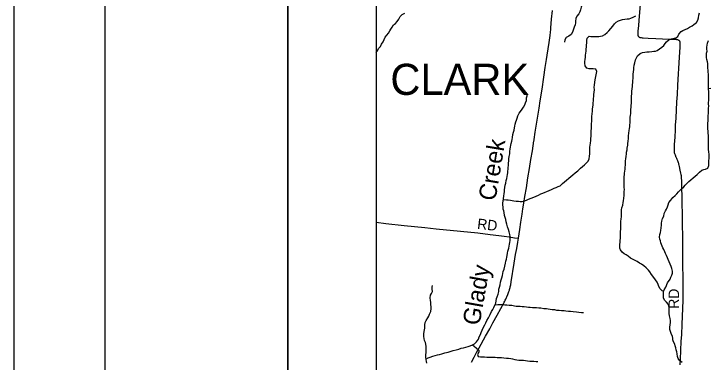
# Model space of a CAD drawing. Extents: x 0 to 1052, y -194 to 246.
# Drawn here: x 0 to 3.805, y 17.846 to 19.749 of the extents above; entities that cross this region are included whole.
import ezdxf

# ---------------------------------------------------------------- set-up
doc = ezdxf.new("R2010")
doc.units = 0
for name, color, linetype in [('GM_X_Corporation', 7, 'Continuous'), ('GM_X_County_Road', 7, 'Continuous'), ('GM_X_County_Road_Text', 7, 'Continuous'), ('GM_X_Minor_River', 7, 'Continuous'), ('GM_X_Minor_River_Text', 7, 'Continuous'), ('GM_X_Township_Road', 7, 'Continuous'), ('GM_X_Township_Road_Text', 7, 'Continuous'), ('GM_X_Township_Text', 7, 'Continuous'), ('SH_Border', 7, 'Continuous'), ('SH_Cut_Line', 7, 'Continuous')]:
    doc.layers.add(name, color=color, linetype=linetype)

msp = doc.modelspace()

# ---------------------------------------------------------------- linework, layer by layer
at = {"layer": 'GM_X_Corporation'}
for points in [[(5.1788, 17.6981), (5.491, 17.9457), (6.1888, 18.4644), (6.5994, 18.7694), (6.8785, 18.9763), (8.1871, 19.9814), (8.6571, 20.341), (8.7822, 20.435), (8.7822, 21.0055), (1.9822, 21.0055), (1.9822, 14.2055)], [(5.1788, 17.6981), (5.491, 17.9457), (6.1888, 18.4644), (6.152, 18.6129), (5.992, 19.3448), (5.9283, 19.6076), (5.6935, 20.5776), (5.5898, 21.0055), (1.9822, 21.0055), (1.9822, 14.2055)]]:
    msp.add_lwpolyline(points, dxfattribs=at)
at = {"layer": 'GM_X_County_Road'}
for points in [[(3.6466, 17.8318), (3.6482, 17.8609), (3.6507, 17.9105), (3.653, 17.9577), (3.6552, 17.9974), (3.6578, 18.0507), (3.6604, 18.0979), (3.6618, 18.1389), (3.6628, 18.1849), (3.6633, 18.2296), (3.6634, 18.2607), (3.6626, 18.3346), (3.6623, 18.3483), (3.6622, 18.3526), (3.6623, 18.3675), (3.662, 18.4222), (3.6617, 18.4899), (3.6611, 18.5303), (3.6599, 18.5999), (3.6591, 18.6558), (3.6579, 18.7117), (3.657, 18.7621), (3.6564, 18.7851), (3.6552, 18.841), (3.6548, 18.8498), (3.6546, 18.8534), (3.6542, 18.8582), (3.6538, 18.8621), (3.6533, 18.8656), (3.6529, 18.8683), (3.6524, 18.8708), (3.651, 18.8781), (3.6474, 18.8945), (3.6426, 18.9157), (3.6411, 18.9224), (3.6401, 18.9265), (3.639, 18.9309), (3.6375, 18.936), (3.636, 18.9411), (3.6344, 18.9454), (3.6328, 18.9499), (3.6309, 18.9542), (3.629, 18.9584), (3.6274, 18.9617), (3.6257, 18.9651), (3.6205, 18.9764), (3.6189, 18.9807), (3.6177, 18.9847), (3.6166, 18.9893), (3.6159, 18.9929), (3.6155, 18.9971), (3.6152, 19.0005), (3.615, 19.0039), (3.6151, 19.0092), (3.6152, 19.0132), (3.6156, 19.0206), (3.6164, 19.0349), (3.6187, 19.0764), (3.6207, 19.1149), (3.622, 19.141), (3.6241, 19.1788), (3.629, 19.2688), (3.6314, 19.3091), (3.6341, 19.36), (3.6429, 19.5125), (3.646, 19.5684), (3.647, 19.5815), (3.6471, 19.5865), (3.6472, 19.5903), (3.647, 19.5936), (3.6465, 19.5963), (3.6457, 19.5986), (3.6446, 19.6004), (3.6431, 19.6021), (3.6416, 19.6033), (3.6398, 19.6047), (3.6376, 19.6059), (3.6345, 19.6071), (3.6315, 19.6079), (3.6292, 19.6083), (3.6264, 19.6086), (3.5934, 19.6098), (3.5499, 19.6121), (3.5133, 19.6137), (3.4724, 19.6157), (3.4444, 19.6173), (3.4407, 19.6175), (3.4352, 19.6181), (3.4316, 19.6186), (3.4287, 19.6193), (3.4262, 19.6202), (3.4243, 19.6213), (3.4224, 19.6225), (3.4207, 19.6242), (3.419, 19.6264), (3.418, 19.6283), (3.4173, 19.6302), (3.4167, 19.6331), (3.4165, 19.635), (3.4163, 19.6373), (3.4164, 19.6404), (3.4164, 19.6428), (3.4169, 19.6484), (3.4176, 19.6552), (3.4202, 19.6855), (3.4225, 19.7127), (3.4324, 19.8272)], [(2.7611, 18.5232), (2.7689, 18.5716), (2.7753, 18.6114), (2.782, 18.6544), (2.7864, 18.6839), (2.7915, 18.7152), (2.797, 18.7508), (2.8049, 18.7992), (2.8138, 18.8538), (2.8223, 18.9047), (2.8298, 18.9526), (2.8378, 19.001), (2.8463, 19.056), (2.8469, 19.0593), (2.8475, 19.063), (2.8539, 19.1029), (2.8594, 19.1353), (2.8694, 19.2004), (2.8743, 19.2336), (2.8806, 19.2748), (2.8906, 19.3386), (2.9007, 19.4043), (2.9085, 19.456), (2.912, 19.4787), (2.9152, 19.5002), (2.919, 19.5247), (2.9295, 19.5935), (2.9346, 19.6311), (2.9368, 19.6488), (2.9374, 19.6539), (2.9381, 19.6604), (2.9393, 19.673), (2.9433, 19.7201), (2.948, 19.7683)], [(2.5041, 17.8459), (2.5187, 17.8727), (2.5324, 17.8977), (2.5464, 17.9234), (2.5817, 17.9869), (2.6044, 18.0283), (2.6218, 18.0599), (2.6455, 18.1022), (2.6653, 18.1388), (2.6816, 18.1688), (2.6842, 18.1739), (2.687, 18.1794), (2.6895, 18.1843), (2.6921, 18.1897), (2.6964, 18.1988), (2.6984, 18.2034), (2.7034, 18.2147), (2.7077, 18.2257), (2.7098, 18.2316), (2.711, 18.235), (2.7124, 18.2396), (2.7135, 18.2433), (2.7147, 18.2479), (2.716, 18.2529), (2.7171, 18.258), (2.718, 18.2626), (2.7191, 18.2686), (2.7202, 18.2749), (2.7209, 18.2791), (2.7219, 18.2853), (2.7383, 18.3864), (2.746, 18.4337), (2.752, 18.4673), (2.7578, 18.5022), (2.7611, 18.5232)]]:
    msp.add_lwpolyline(points, dxfattribs=at)
at = {"layer": 'GM_X_Minor_River'}
for points in [[(3.1551, 19.8769), (3.1466, 19.8642), (3.1365, 19.8514), (3.1295, 19.8386), (3.124, 19.825), (3.1151, 19.8122), (3.1089, 19.7993), (3.1049, 19.7865), (3.1005, 19.7717), (3.0977, 19.7611), (3.0923, 19.7502), (3.0815, 19.7374), (3.0763, 19.725), (3.0743, 19.7102), (3.073, 19.7003), (3.0717, 19.6905), (3.0666, 19.6761), (3.0611, 19.6614), (3.0567, 19.6497), (3.0501, 19.6369), (3.0371, 19.6275), (3.0233, 19.6205), (3.0163, 19.6073), (3.0139, 19.5952)], [(1.9822, 19.5386), (1.9877, 19.5466), (1.9966, 19.5613), (2.0062, 19.5714), (2.0124, 19.5831), (2.0214, 19.5959), (2.0265, 19.6091), (2.0327, 19.6227), (2.0416, 19.6332), (2.0505, 19.6445), (2.0579, 19.6562), (2.0637, 19.6667), (2.0703, 19.6776), (2.0781, 19.6901), (2.088, 19.6975), (2.0977, 19.7073), (2.1062, 19.7208), (2.1148, 19.7359), (2.1259, 19.7464), (2.1389, 19.7542)], [(3.3877, 19.3736), (3.3882, 19.3842), (3.3892, 19.3979), (3.3897, 19.4096), (3.3902, 19.4203), (3.3915, 19.432), (3.3925, 19.4453), (3.393, 19.4548), (3.3954, 19.4684), (3.3987, 19.4824), (3.4023, 19.4983), (3.4074, 19.51), (3.414, 19.5202), (3.4274, 19.5329), (3.4415, 19.5377), (3.4541, 19.5409), (3.4648, 19.5415), (3.4766, 19.5421), (3.4921, 19.5438), (3.502, 19.5448), (3.5115, 19.5462), (3.5215, 19.5491), (3.5345, 19.5577), (3.5464, 19.5667), (3.5572, 19.5772), (3.5645, 19.5869), (3.5715, 19.5975), (3.5861, 19.6098), (3.6002, 19.6138), (3.6139, 19.6159), (3.6234, 19.6188), (3.6338, 19.6263), (3.6389, 19.638), (3.6524, 19.6537), (3.6619, 19.6586), (3.6738, 19.6633), (3.6875, 19.6696), (3.6983, 19.6763), (3.7116, 19.6841), (3.7224, 19.6908), (3.7354, 19.7024), (3.7436, 19.7148), (3.7468, 19.7281), (3.7496, 19.7421), (3.7532, 19.7557)], [(3.1916, 19.6255), (3.2011, 19.6266), (3.211, 19.6283), (3.2213, 19.6297), (3.2343, 19.636), (3.2478, 19.6476), (3.2566, 19.6574), (3.267, 19.6694), (3.2779, 19.6825), (3.2871, 19.6957), (3.2971, 19.705), (3.3086, 19.7117), (3.3205, 19.7157), (3.3311, 19.7183), (3.3441, 19.72), (3.3562, 19.7217), (3.3673, 19.7231), (3.3776, 19.7264), (3.3902, 19.7315), (3.4039, 19.7382)], [(2.6791, 18.7342), (2.6958, 18.7334), (2.7061, 18.7325), (2.7178, 18.7305), (2.7277, 18.7292), (2.7372, 18.7275), (2.7493, 18.7266), (2.7611, 18.7257), (2.7717, 18.7241), (2.7812, 18.7232), (2.7945, 18.7268), (2.8052, 18.732), (2.8167, 18.736), (2.8319, 18.7426), (2.8453, 18.7482), (2.8579, 18.7529), (2.8705, 18.7581), (2.8847, 18.7655), (2.8942, 18.7692), (2.908, 18.7747), (2.9175, 18.7791), (2.9297, 18.7847), (2.9424, 18.7902), (2.9573, 18.7972), (2.968, 18.8012), (2.9798, 18.8056), (2.9901, 18.8101), (3.0024, 18.8217), (3.0128, 18.8314), (3.0239, 18.8396), (3.037, 18.852), (3.0485, 18.8602), (3.06, 18.8699), (3.0727, 18.88), (3.0861, 18.8912), (3.1015, 18.9062), (3.1115, 18.9152), (3.1223, 18.9249), (3.1327, 18.9327), (3.1431, 18.944), (3.1493, 18.9568), (3.1514, 18.9716), (3.1524, 18.9849), (3.1527, 19.008), (3.1532, 19.0205), (3.1545, 19.0315), (3.1554, 19.0422), (3.1571, 19.0577), (3.1584, 19.0683), (3.1593, 19.0808), (3.1605, 19.1104), (3.1614, 19.1226), (3.1616, 19.1381), (3.1621, 19.148), (3.1631, 19.1632), (3.1636, 19.1761), (3.1642, 19.1905), (3.1655, 19.2015), (3.1665, 19.2189), (3.1678, 19.2307), (3.169, 19.2401), (3.17, 19.2523), (3.1712, 19.2625), (3.1725, 19.275), (3.1731, 19.2868), (3.1744, 19.2978), (3.1749, 19.308), (3.1762, 19.3209), (3.1771, 19.3349), (3.1769, 19.3482), (3.1775, 19.3604), (3.18, 19.3759), (3.182, 19.3884), (3.1837, 19.3983), (3.1861, 19.4081), (3.1894, 19.4251), (3.1906, 19.4354), (3.1847, 19.4468), (3.1714, 19.4485), (3.1619, 19.4486), (3.149, 19.4496), (3.1362, 19.4535), (3.1261, 19.4647), (3.1248, 19.4799), (3.1256, 19.4894), (3.1273, 19.5), (3.1286, 19.5132), (3.1291, 19.5239), (3.1304, 19.5341), (3.1321, 19.5466), (3.133, 19.5568), (3.1335, 19.569), (3.1344, 19.5792), (3.1353, 19.591), (3.1367, 19.6046), (3.1383, 19.6167), (3.1484, 19.6272), (3.1578, 19.6267), (3.1715, 19.6262), (3.181, 19.6257), (3.1916, 19.6255)], [(3.5406, 18.5649), (3.5431, 18.5804), (3.5448, 18.5945), (3.5446, 18.6055), (3.5459, 18.6172), (3.5506, 18.6308), (3.5565, 18.644), (3.5601, 18.6588), (3.566, 18.672), (3.5718, 18.6826), (3.5766, 18.6954), (3.5813, 18.706), (3.5856, 18.7185), (3.5953, 18.7305), (3.6073, 18.7463), (3.6188, 18.756), (3.6284, 18.7661), (3.638, 18.7759), (3.6523, 18.792), (3.6661, 18.8032), (3.6739, 18.8134), (3.6843, 18.8242), (3.695, 18.834), (3.705, 18.8429), (3.7177, 18.8538), (3.7288, 18.8628), (3.7392, 18.8706), (3.7527, 18.8848), (3.7661, 18.8945), (3.7757, 18.899), (3.7852, 18.9004), (3.7982, 18.9059), (3.8029, 18.9199), (3.8039, 18.9358), (3.8044, 18.9487), (3.805, 18.9589), (3.8047, 18.9715), (3.8049, 18.9817), (3.8039, 18.9946), (3.8026, 19.0083), (3.8023, 19.0193), (3.8018, 19.0342), (3.8015, 19.0444), (3.8017, 19.0539), (3.8014, 19.0649), (3.8016, 19.0771), (3.801, 19.0866), (3.8007, 19.0964), (3.7997, 19.1075), (3.7991, 19.1204), (3.7981, 19.1306), (3.7979, 19.1413), (3.7984, 19.1538), (3.7997, 19.1633), (3.8002, 19.1731), (3.8, 19.1834), (3.8005, 19.1929), (3.8018, 19.2061), (3.802, 19.2213), (3.8025, 19.2316), (3.8031, 19.246), (3.8024, 19.2555), (3.8022, 19.2657), (3.8031, 19.2756), (3.804, 19.2858), (3.8042, 19.3048), (3.8036, 19.3147), (3.803, 19.3257), (3.8024, 19.3371), (3.8025, 19.347), (3.8023, 19.3565), (3.8017, 19.3694), (3.8026, 19.3807), (3.802, 19.3918), (3.8014, 19.4054), (3.8012, 19.4202), (3.8006, 19.4301), (3.8, 19.4427), (3.7986, 19.4522), (3.798, 19.4658), (3.7974, 19.478), (3.7964, 19.4883), (3.7932, 19.5008), (3.7918, 19.5103), (3.7904, 19.5248), (3.7917, 19.5343), (3.7941, 19.5464), (3.7935, 19.557), (3.7929, 19.5673), (3.7946, 19.5779), (3.7962, 19.5892), (3.8017, 19.6032)], [(3.5563, 18.233), (3.548, 18.2364), (3.5367, 18.2461), (3.5293, 18.2598), (3.5264, 18.2694), (3.5209, 18.282), (3.5123, 18.2961), (3.5026, 18.3092), (3.4903, 18.3241), (3.4806, 18.3387), (3.4728, 18.3486), (3.4616, 18.3621), (3.4484, 18.3729), (3.4352, 18.3818), (3.4243, 18.3876), (3.4115, 18.3954), (3.4006, 18.4016), (3.3889, 18.4074), (3.3753, 18.4148), (3.3629, 18.4256), (3.3512, 18.4326), (3.3407, 18.4384), (3.3286, 18.4477), (3.3201, 18.4596), (3.3171, 18.4691), (3.3169, 18.4786), (3.3174, 18.4904), (3.3183, 18.5002), (3.3192, 18.5116), (3.3197, 18.5215), (3.3199, 18.5359), (3.3194, 18.5496), (3.3203, 18.5609), (3.3212, 18.5715), (3.3213, 18.5826), (3.3219, 18.5943), (3.322, 18.6068), (3.3229, 18.6167), (3.3242, 18.6277), (3.3248, 18.6414), (3.3253, 18.6558), (3.3259, 18.6679), (3.3264, 18.6789), (3.3277, 18.6895), (3.3321, 18.7035), (3.3357, 18.7179), (3.3369, 18.7277), (3.3379, 18.7414), (3.3396, 18.7558), (3.3405, 18.766), (3.3407, 18.7793), (3.3412, 18.7896), (3.3406, 18.7998), (3.3403, 18.8116), (3.3397, 18.8241), (3.3407, 18.8359), (3.3404, 18.848), (3.3402, 18.8598), (3.3419, 18.8697), (3.3428, 18.8795), (3.3437, 18.8905), (3.3453, 18.9004), (3.3466, 18.9114), (3.3471, 18.9216), (3.3477, 18.9337), (3.3482, 18.9463), (3.3495, 18.9576), (3.3508, 18.9705), (3.3529, 18.9838), (3.3538, 18.9933), (3.3562, 19.0061), (3.3571, 19.0156), (3.3596, 19.0315), (3.3609, 19.0418), (3.3622, 19.0531), (3.3631, 19.0683), (3.3645, 19.0827), (3.3666, 19.0967), (3.3675, 19.1115), (3.3699, 19.1225), (3.3708, 19.1328), (3.3713, 19.1426), (3.3726, 19.154), (3.3735, 19.1638), (3.3738, 19.184), (3.3747, 19.1934), (3.376, 19.2044), (3.3765, 19.2147), (3.3774, 19.228), (3.3783, 19.2374), (3.3788, 19.2484), (3.3801, 19.2606), (3.38, 19.2761), (3.3805, 19.2868), (3.3806, 19.2989), (3.3823, 19.3122), (3.3829, 19.327), (3.3835, 19.3391), (3.3851, 19.352), (3.386, 19.3618), (3.3877, 19.3736)], [(3.8025, 19.3424), (3.8154, 19.3426)], [(2.7082, 18.9451), (2.7095, 18.9564), (2.7115, 18.9705), (2.714, 18.9837), (2.7149, 18.997), (2.7166, 19.011), (2.7179, 19.0216), (2.72, 19.0315), (2.7224, 19.0413), (2.7248, 19.053), (2.7268, 19.0636), (2.7285, 19.0743), (2.7317, 19.0902), (2.735, 19.103), (2.7374, 19.1136), (2.7398, 19.1257), (2.7422, 19.1363), (2.7443, 19.1466), (2.7475, 19.1587), (2.7506, 19.1685), (2.7538, 19.1795), (2.7582, 19.1931), (2.7648, 19.2063), (2.7729, 19.2164), (2.7815, 19.2285), (2.7892, 19.2401), (2.7966, 19.2526), (2.8009, 19.2635), (2.8049, 19.2767), (2.8066, 19.29), (2.8094, 19.3017), (2.8107, 19.3116)], [(2.2555, 17.8624), (2.2679, 17.8696), (2.2786, 17.8725), (2.2927, 17.8776), (2.3053, 17.8816), (2.3179, 17.8853), (2.3286, 17.8878), (2.3419, 17.8914), (2.3587, 17.8957), (2.3762, 17.9008), (2.3877, 17.9033), (2.4052, 17.9088), (2.4212, 17.9135), (2.4361, 17.9175), (2.4479, 17.9212), (2.4601, 17.9248), (2.4731, 17.9284), (2.486, 17.9313), (2.4979, 17.9353), (2.5109, 17.9405), (2.5219, 17.946), (2.5327, 17.9573), (2.5428, 17.9716), (2.5468, 17.984), (2.5538, 17.9965), (2.5577, 18.0082), (2.5628, 18.0207), (2.5703, 18.0361), (2.5773, 18.0501), (2.5827, 18.0603), (2.5886, 18.0739), (2.5975, 18.0882), (2.6065, 18.107), (2.6147, 18.1217), (2.621, 18.1342), (2.6272, 18.1451), (2.6327, 18.1579), (2.637, 18.1681), (2.6415, 18.1931), (2.6454, 18.203), (2.6509, 18.2177), (2.6534, 18.2313), (2.6551, 18.2438), (2.6579, 18.2548), (2.6611, 18.2692), (2.664, 18.2828), (2.6672, 18.2957), (2.6704, 18.3063), (2.6743, 18.3191), (2.6768, 18.3297), (2.6781, 18.3411), (2.6832, 18.3543), (2.6872, 18.3698), (2.6912, 18.3861), (2.6932, 18.3982), (2.6957, 18.4084), (2.6985, 18.4194), (2.6997, 18.4289), (2.7018, 18.4406), (2.7039, 18.4527), (2.7086, 18.4683), (2.7114, 18.4788), (2.7135, 18.4902), (2.7144, 18.4997), (2.716, 18.5099), (2.7162, 18.5224), (2.7159, 18.5323), (2.7142, 18.5437), (2.711, 18.5582), (2.7073, 18.5704), (2.7022, 18.5853), (2.6982, 18.6001), (2.695, 18.6131), (2.6921, 18.626), (2.6892, 18.6363), (2.6856, 18.6481), (2.6831, 18.663), (2.681, 18.6732), (2.6788, 18.6827), (2.6774, 18.6926), (2.6765, 18.7048), (2.677, 18.7166), (2.6783, 18.7264), (2.6796, 18.7393), (2.6821, 18.7541), (2.6834, 18.7654), (2.6847, 18.778), (2.6856, 18.7878), (2.6876, 18.7996), (2.6897, 18.8124), (2.6917, 18.8234), (2.695, 18.8382), (2.6978, 18.8488), (2.7011, 18.8708), (2.7027, 18.881), (2.7036, 18.8905), (2.7049, 18.8999), (2.7058, 18.9098), (2.7071, 18.9212), (2.7073, 18.9344), (2.7082, 18.9451)], [(3.6578, 17.8436), (3.6454, 17.8536), (3.6365, 17.8659), (3.6324, 17.877), (3.63, 17.8918), (3.6286, 17.9021), (3.6257, 17.9127), (3.6224, 17.9242), (3.6203, 17.9345), (3.617, 17.944), (3.6107, 17.9562), (3.6074, 17.9673), (3.6064, 17.9768), (3.6047, 17.9867), (3.5984, 18.0027), (3.5936, 18.0126), (3.59, 18.0233), (3.5898, 18.0362), (3.5922, 18.0495), (3.5947, 18.0623), (3.5941, 18.073), (3.5912, 18.0848), (3.5887, 18.0981), (3.587, 18.1114), (3.5871, 18.1239), (3.5862, 18.1353), (3.5863, 18.1448), (3.5823, 18.1604), (3.5726, 18.1739), (3.5602, 18.1846), (3.5555, 18.1972), (3.5549, 18.2098), (3.5562, 18.2223), (3.5559, 18.2318), (3.5591, 18.2416), (3.5676, 18.2559), (3.5782, 18.2797), (3.5914, 18.3), (3.5965, 18.3106), (3.6012, 18.3204), (3.6048, 18.3325), (3.6045, 18.3435), (3.6013, 18.3568), (3.5976, 18.369), (3.5914, 18.3816), (3.5858, 18.3935), (3.5811, 18.4061), (3.577, 18.416), (3.5711, 18.4294), (3.5663, 18.4393), (3.5623, 18.4488), (3.5579, 18.4614), (3.5523, 18.4714), (3.5442, 18.4886), (3.5409, 18.4988), (3.5384, 18.5084), (3.5362, 18.5183), (3.5345, 18.5293), (3.5362, 18.5437), (3.5397, 18.5539), (3.5406, 18.5649)], [(2.2456, 18.0141), (2.2489, 18.0323), (2.2498, 18.0494), (2.2512, 18.063), (2.2563, 18.074), (2.2652, 18.0872), (2.2714, 18.0969), (2.2749, 18.1075), (2.2812, 18.1226), (2.2837, 18.1382), (2.2842, 18.148), (2.2829, 18.1613), (2.2819, 18.1727), (2.2794, 18.183), (2.2777, 18.1975), (2.2809, 18.2111), (2.2852, 18.2217), (2.2903, 18.2326), (2.2889, 18.2455), (2.2895, 18.2554), (2.2911, 18.2652)], [(2.6335, 18.1598), (2.6487, 18.1612), (2.6616, 18.1614), (2.6741, 18.1612), (2.6862, 18.1595), (2.6973, 18.1594), (2.7117, 18.1573), (2.7253, 18.1564), (2.7397, 18.1535), (2.7492, 18.1519), (2.7613, 18.151), (2.7712, 18.1508), (2.7815, 18.1503), (2.7936, 18.149), (2.8054, 18.1481), (2.816, 18.1468), (2.8266, 18.1456), (2.8387, 18.1446), (2.8501, 18.1445), (2.8604, 18.1436), (2.8737, 18.1427), (2.8839, 18.1418), (2.9002, 18.1397), (2.9143, 18.1384), (2.9241, 18.1371), (2.9351, 18.135), (2.9465, 18.1341), (2.9594, 18.1328), (2.9704, 18.1304), (2.9844, 18.1291), (2.9973, 18.1282), (3.011, 18.1272), (3.0208, 18.1256), (3.036, 18.125), (3.0459, 18.1241), (3.0618, 18.1224), (3.0785, 18.1203), (3.0929, 18.1182), (3.1073, 18.1176), (3.1168, 18.1171)], [(2.2599, 17.8393), (2.2578, 17.8488), (2.2557, 17.8595), (2.2551, 17.872), (2.2552, 17.8842), (2.2558, 17.9001), (2.256, 17.9115), (2.2569, 17.9221), (2.2559, 17.932), (2.2541, 17.9438), (2.252, 17.9533), (2.2483, 17.964), (2.2447, 17.9743), (2.2429, 17.9861), (2.2443, 18.0012), (2.2456, 18.0141)], [(2.511, 17.9405), (2.5199, 17.9328), (2.5326, 17.9223), (2.5443, 17.9119), (2.5457, 17.9009), (2.5383, 17.8881), (2.5415, 17.8767), (2.554, 17.8742), (2.5643, 17.8745), (2.5761, 17.8743), (2.5894, 17.8738), (2.6004, 17.8733), (2.6114, 17.8735), (2.6239, 17.873), (2.6334, 17.8721), (2.6452, 17.8715), (2.6558, 17.8718), (2.6695, 17.8708), (2.6808, 17.8692), (2.6956, 17.8675), (2.7074, 17.8666), (2.7199, 17.8649), (2.7294, 17.8644), (2.7415, 17.8604), (2.7521, 17.8591), (2.7631, 17.8571), (2.7764, 17.8569), (2.7889, 17.856), (2.801, 17.854), (2.8117, 17.8523), (2.8234, 17.8518), (2.8359, 17.8508), (2.8462, 17.8503), (2.858, 17.8498), (2.8675, 17.8493)]]:
    msp.add_lwpolyline(points, dxfattribs=at)
at = {"layer": 'GM_X_Township_Road'}
msp.add_lwpolyline([(1.9822, 18.6104), (2.0354, 18.6045), (2.1354, 18.5933), (2.2485, 18.5812), (2.3109, 18.5746), (2.4438, 18.5611), (2.539, 18.5517), (2.6063, 18.5441), (2.6544, 18.538), (2.6834, 18.5342), (2.7105, 18.5304), (2.7406, 18.5261), (2.7611, 18.5232)], dxfattribs=at)
at = {"layer": 'SH_Border'}
for points in [[(0.5, 21.5), (1.5, 21.5), (1.5, 0.5), (0.5, 0.5)], [(1.5, 21.5), (33.5, 21.5), (33.5, 0.5), (1.5, 0.5)]]:
    msp.add_lwpolyline(points, close=True, dxfattribs=at)
at = {"layer": 'SH_Cut_Line'}
msp.add_lwpolyline([(0, 0), (34, 0), (34, 22), (0, 22)], close=True, dxfattribs=at)

# ---------------------------------------------------------------- texts
at = {"layer": 'GM_X_County_Road_Text'}
msp.add_text('RD', height=0.05682, rotation=89.5254, dxfattribs=at).set_placement((3.6399, 18.1375))
at = {"layer": 'GM_X_Minor_River_Text'}
for s, rotation, p in [('Creek', 80.5946, (2.6354, 18.7236)), ('Glady', 80.0003, (2.5483, 18.0424))]:
    msp.add_text(s, height=0.0947, rotation=rotation, dxfattribs=at).set_placement(p)
at = {"layer": 'GM_X_Township_Road_Text'}
msp.add_text('RD', height=0.05682, rotation=353.5519, dxfattribs=at).set_placement((2.5338, 18.575))
at = {"layer": 'GM_X_Township_Text'}
msp.add_text('CLARK', height=0.17045, rotation=0, dxfattribs=at).set_placement((2.0605, 19.3065))

doc.saveas('drawing.dxf')
